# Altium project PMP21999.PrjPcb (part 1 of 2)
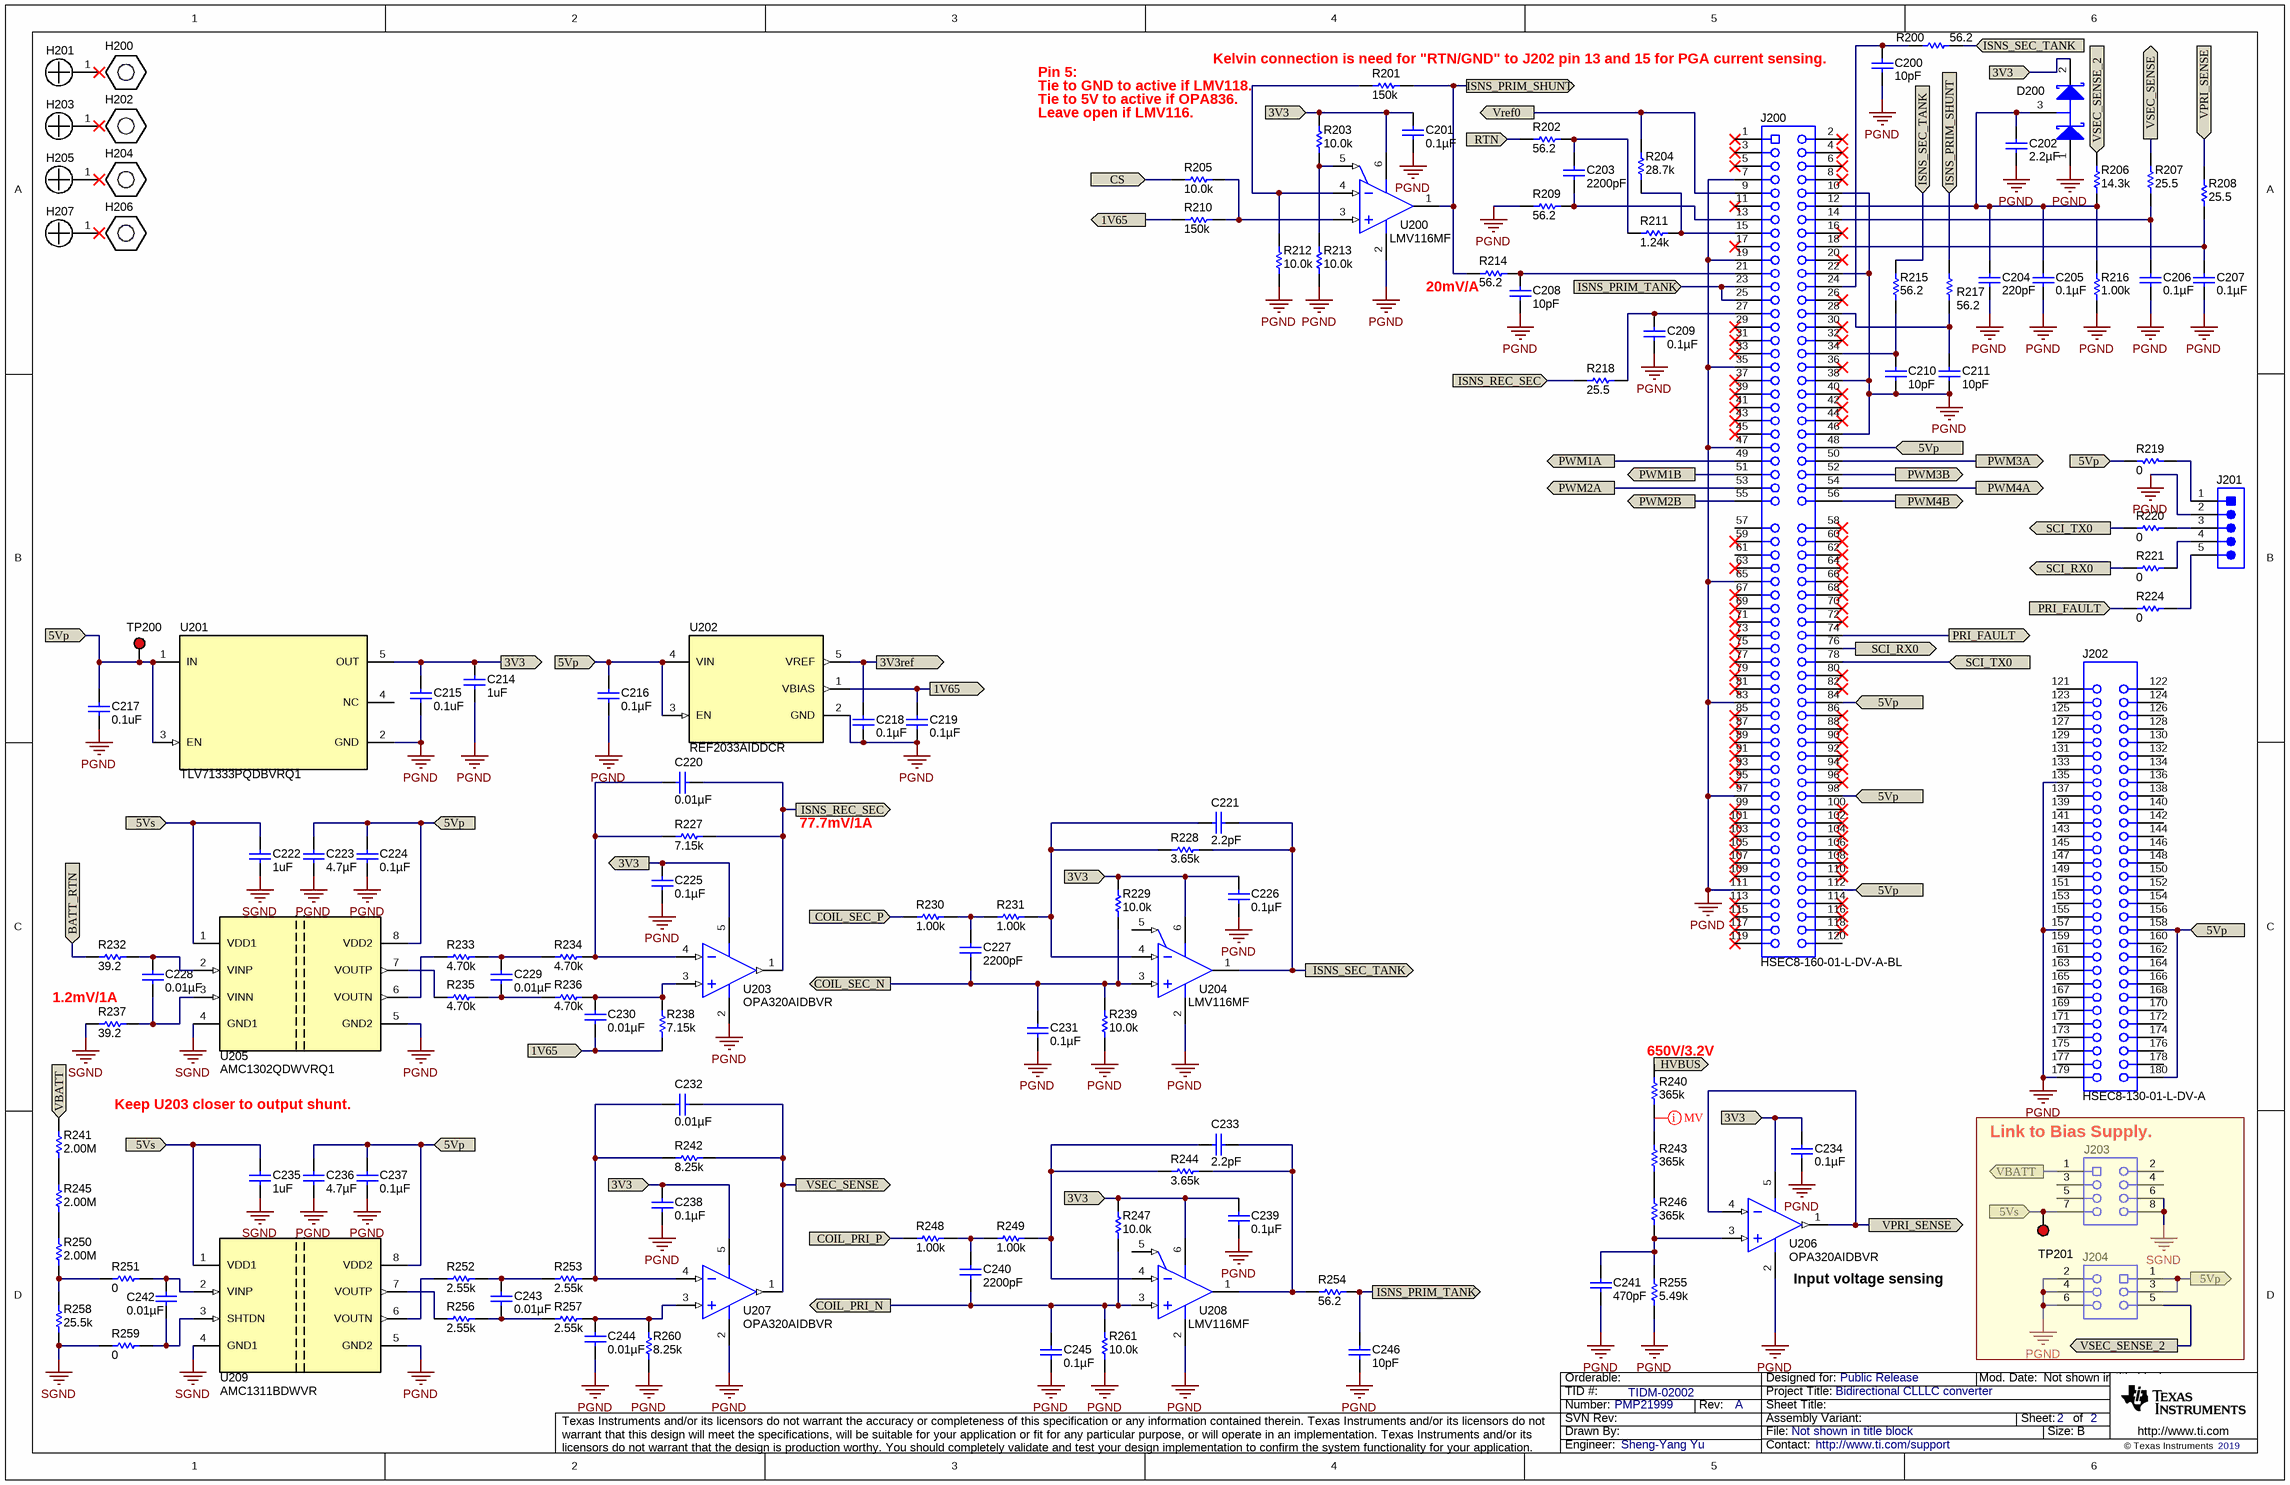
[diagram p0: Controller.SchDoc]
CopyrightYear: 2019; PCB_Layout: Sheng-Yang Yu; PCB_Rev: A; PRJ_Customer: Public Release; PRJ_Engineer: Sheng-Yang Yu; PRJ_Number: PMP21999; PRJ_Title: Bidirectional CLLLC converter; SCH_Rev: A; TechSupport: http://www.ti.com/support; TID: TIDM-02002
2 sheets, 250 parts. Net scope: flat (ports and power ports of the same name join across sheets).
Board file: PMP21999.PcbDoc
Sheets:
  Controller.SchDoc
  PowerStage.SchDoc

## Sheet Controller.SchDoc
size 431 x 279 mm; Date: Not shown in title block; ApprovedBy: Not shown in title block; CheckedBy: Not shown in title block; Author: Not shown in title block; CompanyName: Not shown in title block; Engineer: Not shown in title block; Organization: Not shown in title block; Address1: Not shown in title block; Address2: Not shown in title block; Address3: Not shown in title block; Address4: Not shown in title block; DocumentNumber: 2; Revision: Use project parameter SCH_Rev; SheetNumber: 2; SheetTotal: 2; PageSetup: Record=PageOptions¦CenterHorizontal=True¦CenterVertical=True¦PrintScale=1.00¦XCorrection=1.00¦YCorrection=1.00¦PrintKind=0¦BorderSize=5000000¦LeftOffset=0¦BottomOffset=0¦Orientation=2¦PaperLength=1000¦PaperWidth=1000¦Scale=100¦PaperSource=15¦PrintQuality=600¦MediaType=1¦DitherType=10¦PaperKind=Letter¦PrintScaleMode=1

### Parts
C200  ValueDisplayed: 10pF  [0402]  (hidden comment: C0402C100C8GACTU)
C201  ValueDisplayed: 0.1µF  [0603]  (hidden comment: 06033C104JAT2A)
C202  ValueDisplayed: 2.2µF  [0603]  (hidden comment: GRM188C80J225KE19D)
C203  ValueDisplayed: 2200pF  [0402]  (hidden comment: C0402C222K9RAC7867)
C204  ValueDisplayed: 220pF  [0402]  (hidden comment: AC0402KRX7R9BB221)
C205  ValueDisplayed: 0.1µF  [0603]  (hidden comment: 06033C104JAT2A)
C206  ValueDisplayed: 0.1µF  [0603]  (hidden comment: 06033C104JAT2A)
C207  ValueDisplayed: 0.1µF  [0402]  (hidden comment: C1005X7R1E104M050BB)
C208  ValueDisplayed: 10pF  [0603]  (hidden comment: C0603C100J5GACTU)
C209  ValueDisplayed: 0.1µF  [0603]  (hidden comment: 06033C104JAT2A)
C210  ValueDisplayed: 10pF  [0402]  (hidden comment: C0402C100C8GACTU)
C211  ValueDisplayed: 10pF  [0402]  (hidden comment: C0402C100C8GACTU)
C214  ValueDisplayed: 1uF  [0603]  (hidden comment: C1608X7R1E105K080AB)
C215  ValueDisplayed: 0.1uF  [0402]  (hidden comment: CC0402KRX7R5BB104)
C216  ValueDisplayed: 0.1µF  [0603]  (hidden comment: 06033C104JAT2A)
C217  ValueDisplayed: 0.1uF  [0402]  (hidden comment: CC0402KRX7R5BB104)
C218  ValueDisplayed: 0.1µF  [0603]  (hidden comment: 06033C104JAT2A)
C219  ValueDisplayed: 0.1µF  [0603]  (hidden comment: 06033C104JAT2A)
C220  ValueDisplayed: 0.01µF  [0402]  (hidden comment: GRM155R61A103KA01D)
C221  ValueDisplayed: 2.2pF  [0402]  (hidden comment: GRM1555C1H2R2BA01D)
C222  ValueDisplayed: 1uF  [0603]  (hidden comment: C1608X7R1E105K080AB)
C223  ValueDisplayed: 4.7µF  [0603]  (hidden comment: CGB3B1X5R1A475K055AC)
C224  ValueDisplayed: 0.1µF  [0603]  (hidden comment: 06033C104JAT2A)
C225  ValueDisplayed: 0.1µF  [0402]  (hidden comment: C1005X7R1E104M050BB)
C226  ValueDisplayed: 0.1µF  [0402]  (hidden comment: 0402YC104KAT2A)
C227  ValueDisplayed: 2200pF  [0402]  (hidden comment: CGA2B2X7R1H222K050BA)
C228  ValueDisplayed: 0.01µF  [0603]  (hidden comment: 06031C103KAT2A)
C229  ValueDisplayed: 0.01µF  [0402]  (hidden comment: GRM155R61A103KA01D)
C230  ValueDisplayed: 0.01µF  [0402]  (hidden comment: GRM155R61A103KA01D)
C231  ValueDisplayed: 0.1µF  [0402]  (hidden comment: 0402YC104KAT2A)
C232  ValueDisplayed: 0.01µF  [0402]  (hidden comment: GRM155R61A103KA01D)
C233  ValueDisplayed: 2.2pF  [0402]  (hidden comment: GRM1555C1H2R2BA01D)
C234  ValueDisplayed: 0.1µF  [0805_HV]  (hidden comment: 08053C104JAT2A)
C235  ValueDisplayed: 1uF  [0603]  (hidden comment: C1608X7R1E105K080AB)
C236  ValueDisplayed: 4.7µF  [0603]  (hidden comment: CGB3B1X5R1A475K055AC)
C237  ValueDisplayed: 0.1µF  [0603]  (hidden comment: 06033C104JAT2A)
C238  ValueDisplayed: 0.1µF  [0402]  (hidden comment: C1005X7R1E104M050BB)
C239  ValueDisplayed: 0.1µF  [0402]  (hidden comment: 0402YC104KAT2A)
C240  ValueDisplayed: 2200pF  [0402]  (hidden comment: CGA2B2X7R1H222K050BA)
C241  ValueDisplayed: 470pF  [0402]  (hidden comment: CGA2B2X7R1H471K050BA)
C242  ValueDisplayed: 0.01µF  [0603]  (hidden comment: 06031C103KAT2A)
C243  ValueDisplayed: 0.01µF  [0402]  (hidden comment: GRM155R61A103KA01D)
C244  ValueDisplayed: 0.01µF  [0402]  (hidden comment: GRM155R61A103KA01D)
C245  ValueDisplayed: 0.1µF  [0402]  (hidden comment: 0402YC104KAT2A)
C246  ValueDisplayed: 10pF  [0402]  (hidden comment: C0402C100C8GACTU)
D200  BAT54S-7-F  [SOT-23]  (value not drawn)
H200  1902C  [Keystone_1902C]  (value not drawn)
H201  NY PMS 440 0025 PH  [NY PMS 440 0025 PH]  (value not drawn)
H202  1902C  [Keystone_1902C]  (value not drawn)
H203  NY PMS 440 0025 PH  [NY PMS 440 0025 PH]  (value not drawn)
H204  1902C  [Keystone_1902C]  (value not drawn)
H205  NY PMS 440 0025 PH  [NY PMS 440 0025 PH]  (value not drawn)
H206  1902C  [Keystone_1902C]  (value not drawn)
H207  NY PMS 440 0025 PH  [NY PMS 440 0025 PH]  (value not drawn)
J200  HSEC8-160-01-L-DV-A-BL  [controlCARD-120HSEC]
J201  61300511021  [Wurth_61300511021]  (value not drawn)
J202  HSEC8-130-01-L-DV-A  [controlCARD-180HSEC-60pinAddon]
J203  SSW-104-24-G-D  [Samtec_SSW-104-24-x-D]  (value not drawn)
J204  215307-3  [TE_215307-3]  (value not drawn)
R200  ValueDisplayed: 56.2  [0402]  (hidden comment: RC0402FR-0756R2L)
R201  ValueDisplayed: 150k  [0402]  (hidden comment: CRCW0402150KFKED)
R202  ValueDisplayed: 56.2  [0402]  (hidden comment: RC0402FR-0756R2L)
R203  ValueDisplayed: 10.0k  [0402]  (hidden comment: CRCW040210K0FKED)
R204  ValueDisplayed: 28.7k  [0805_HV]  (hidden comment: CRCW080528K7FKEA)
R205  ValueDisplayed: 10.0k  [0402]  (hidden comment: CRCW040210K0FKED)
R206  ValueDisplayed: 14.3k  [0603]  (hidden comment: CRCW060314K3FKEA)
R207  ValueDisplayed: 25.5  [0603]  (hidden comment: CRCW060325R5FKEA)
R208  ValueDisplayed: 25.5  [0603]  (hidden comment: CRCW060325R5FKEA)
R209  ValueDisplayed: 56.2  [0402]  (hidden comment: RC0402FR-0756R2L)
R210  ValueDisplayed: 150k  [0402]  (hidden comment: CRCW0402150KFKED)
R211  ValueDisplayed: 1.24k  [0402]  (hidden comment: CRCW04021K24FKED)
R212  ValueDisplayed: 10.0k  [0402]  (hidden comment: CRCW040210K0FKED)
R213  ValueDisplayed: 10.0k  [0402]  (hidden comment: CRCW040210K0FKED)
R214  ValueDisplayed: 56.2  [0603]  (hidden comment: CRCW060356R2FKEA)
R215  ValueDisplayed: 56.2  [0402]  (hidden comment: RC0402FR-0756R2L)
R216  ValueDisplayed: 1.00k  [0603]  (hidden comment: CRCW06031K00FKEA)
R217  ValueDisplayed: 56.2  [0402]  (hidden comment: RC0402FR-0756R2L)
R218  ValueDisplayed: 25.5  [0603]  (hidden comment: CRCW060325R5FKEA)
R219  ValueDisplayed: 0  [0603]  (hidden comment: CRCW06030000Z0EA)
R220  ValueDisplayed: 0  [0603]  (hidden comment: CRCW06030000Z0EA)
R221  ValueDisplayed: 0  [0603]  (hidden comment: CRCW06030000Z0EA)
R224  ValueDisplayed: 0  [0603]  (hidden comment: CRCW06030000Z0EA)
R227  ValueDisplayed: 7.15k  [0603]  (hidden comment: CRCW06037K15FKEA)
R228  ValueDisplayed: 3.65k  [0402]  (hidden comment: CRCW04023K65FKED)
R229  ValueDisplayed: 10.0k  [0402]  (hidden comment: CRCW040210K0FKED)
R230  ValueDisplayed: 1.00k  [0402]  (hidden comment: CRCW04021K00FKED)
R231  ValueDisplayed: 1.00k  [0402]  (hidden comment: CRCW04021K00FKED)
R232  ValueDisplayed: 39.2  [0603]  (hidden comment: CRCW060339R2FKEA)
R233  ValueDisplayed: 4.70k  [0402]  (hidden comment: RC0402FR-074K7L)
R234  ValueDisplayed: 4.70k  [0402]  (hidden comment: RC0402FR-074K7L)
R235  ValueDisplayed: 4.70k  [0402]  (hidden comment: RC0402FR-074K7L)
R236  ValueDisplayed: 4.70k  [0402]  (hidden comment: RC0402FR-074K7L)
R237  ValueDisplayed: 39.2  [0603]  (hidden comment: CRCW060339R2FKEA)
R238  ValueDisplayed: 7.15k  [0402]  (hidden comment: CRCW04027K15FKED)
R239  ValueDisplayed: 10.0k  [0402]  (hidden comment: CRCW040210K0FKED)
R240  ValueDisplayed: 365k  [1206]  (hidden comment: CRCW1206365KFKEA)
R241  ValueDisplayed: 2.00M  [1206]  (hidden comment: RC1206FR-072ML)
R242  ValueDisplayed: 8.25k  [0603]  (hidden comment: CRCW06038K25FKEA)
R243  ValueDisplayed: 365k  [1206]  (hidden comment: CRCW1206365KFKEA)
R244  ValueDisplayed: 3.65k  [0402]  (hidden comment: CRCW04023K65FKED)
R245  ValueDisplayed: 2.00M  [1206]  (hidden comment: RC1206FR-072ML)
R246  ValueDisplayed: 365k  [1206]  (hidden comment: CRCW1206365KFKEA)
R247  ValueDisplayed: 10.0k  [0402]  (hidden comment: CRCW040210K0FKED)
R248  ValueDisplayed: 1.00k  [0402]  (hidden comment: CRCW04021K00FKED)
R249  ValueDisplayed: 1.00k  [0402]  (hidden comment: CRCW04021K00FKED)
R250  ValueDisplayed: 2.00M  [1206]  (hidden comment: RC1206FR-072ML)
R251  ValueDisplayed: 0  [0603]  (hidden comment: CRCW06030000Z0EA)
R252  ValueDisplayed: 2.55k  [0603]  (hidden comment: CRCW06032K55FKEA)
R253  ValueDisplayed: 2.55k  [0603]  (hidden comment: CRCW06032K55FKEA)
R254  ValueDisplayed: 56.2  [0402]  (hidden comment: RC0402FR-0756R2L)
R255  ValueDisplayed: 5.49k  [0603]  (hidden comment: CRCW06035K49FKEA)
R256  ValueDisplayed: 2.55k  [0603]  (hidden comment: CRCW06032K55FKEA)
R257  ValueDisplayed: 2.55k  [0603]  (hidden comment: CRCW06032K55FKEA)
R258  ValueDisplayed: 25.5k  [0603]  (hidden comment: CRCW060325K5FKEA)
R259  ValueDisplayed: 0  [0603]  (hidden comment: CRCW06030000Z0EA)
R260  ValueDisplayed: 8.25k  [0603]  (hidden comment: CRCW06038K25FKEA)
R261  ValueDisplayed: 10.0k  [0402]  (hidden comment: CRCW040210K0FKED)
TP200  5000  [Keystone5000]  (value not drawn)
TP201  5000  [Keystone5000]  (value not drawn)
U200  LMV116MF  [DBV0006A_L]
U201  TLV71333PQDBVRQ1  [DBV0005A_N]
U202  REF2033AIDDCR  [DDC0005A_N]
U203  OPA320AIDBVR  [DBV0005A_N]
U204  LMV116MF  [DBV0006A_L]
U205  AMC1302QDWVRQ1  [DWV0008A]
U206  OPA320AIDBVR  [DBV0005A_N]
U207  OPA320AIDBVR  [DBV0005A_N]
U208  LMV116MF  [DBV0006A_L]
U209  AMC1311BDWVR  [DWV0008A]

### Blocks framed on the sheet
Link to Bias Supply.: J203 J204 TP201

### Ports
1V65, 1V65 (in), 1V65 (out), 3V3, 3V3 (in), 3V3 (out), 3V3ref (out), 5Vp, 5Vp (in), 5Vs, BATT_RTN, COIL_PRI_N (out), COIL_PRI_P (in), COIL_SEC_N (out), COIL_SEC_P (in), CS (in), HVBUS (in), ISNS_PRIM_SHUNT (in), ISNS_PRIM_SHUNT (out), ISNS_PRIM_TANK (in), ISNS_PRIM_TANK (out), ISNS_REC_SEC (in), ISNS_REC_SEC (out), ISNS_SEC_TANK (in), ISNS_SEC_TANK (out), PRI_FAULT (in), PRI_FAULT (out), PWM1A, PWM1B, PWM2A (out), PWM2B (out), PWM3A (out), PWM3B (out), PWM4A (out), PWM4B (out), RTN (in), SCI_RX0 (out), SCI_TX0, VBATT, VBATT (in), VPRI_SENSE (in), VPRI_SENSE (out), Vref0 (out), VSEC_SENSE, VSEC_SENSE_2, VSEC_SENSE_2 (out)

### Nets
PGND: C200.2 C201.1 C202.2 C204.2 C205.2 C206.1 C207.2 C208.2 C209.2 C210.2 C211.2 C214.1 C215.2 C216.1 C217.2 C218.1 C219.1 C223.2 C224.1 C225.2 C226.2 C231.2 C234.2 C236.2 C237.1 C238.2 C239.2 C241.2 C244.2 C245.2 C246.2 D200.1(A) J200.7 J200.10 J200.19 J200.22 J200.35 J200.38 J200.46 J200.47 J200.65 J200.83 J200.97 J200.111 J201.2 J202.135 J202.157 J202.179 J204.2 J204.4 J204.6 R209.1 R212.1 R213.1 R216.1 R239.1 R255.1 R260.1 R261.1 U200.2(VS-) U201.2(GND) U202.2(GND) U203.2(V-) U204.2(VS-) U205.5(GND2) U206.2(V-) U207.2(V-) U208.2(VS-) U209.5(GND2)
SGND: C222.1 C235.1 J203.6 J203.8 R237.1 R258.1 R259.1 U205.4(GND1) U209.4(GND1)
1V65: C219.2 C230.2 R210.1 R238.1 U202.1(VBIAS) ; port 1V65
3V3: C201.2 C214.2 C215.1 C225.1 C226.1 C234.1 C238.1 C239.1 D200.2(K) R203.2 R229.2 R247.2 U200.6(VS+) U201.5(OUT) U203.5(V+) U204.6(VS+) U206.5(V+) U207.5(V+) U208.6(VS+) ; port 3V3
3V3ref: C218.2 U202.5(VREF) ; port 3V3ref
5Vp: C216.2 C217.1 C223.1 C224.2 C236.1 C237.2 J200.48 J200.84 J200.98 J200.112 J202.158 J202.180 J204.1 J204.3 R219.2 TP200.1 U201.1(IN) U201.3(EN) U202.3(EN) U202.4(VIN) U205.8(VDD2) U209.8(VDD2) ; port 5Vp
5Vs: C222.2 C235.2 J203.7 TP201.1 U205.1(VDD1) U209.1(VDD1) ; port 5Vs
BATT_RTN: R232.1 ; port BATT_RTN
COIL_PRI_N: C240.2 C245.1 R247.1 R261.2 U208.3(VIN+) ; port COIL_PRI_N
COIL_PRI_P: R248.1 ; port COIL_PRI_P
COIL_SEC_N: C227.2 C231.1 R229.1 R239.2 U204.3(VIN+) ; port COIL_SEC_N
COIL_SEC_P: R230.1 ; port COIL_SEC_P
CS: R205.2 ; port CS
HVBUS: R240.2 ; port HVBUS
ISNS_PRIM_SHUNT: R201.2 R214.1 R217.2 U200.1(VOUT) ; port ISNS_PRIM_SHUNT
ISNS_PRIM_TANK: C246.1 J200.23 J200.25 R254.1 ; port ISNS_PRIM_TANK
ISNS_REC_SEC: C220.1 R218.2 R227.2 U203.1(OUT) ; port ISNS_REC_SEC
ISNS_SEC_TANK: C221.1 R200.2 R215.2 R228.2 U204.1(VOUT) ; port ISNS_SEC_TANK
PRI_FAULT: J200.74 R224.1 ; port PRI_FAULT
PWM1A: J200.49 ; port PWM1A
PWM1B: J200.51 ; port PWM1B
PWM2A: J200.53 ; port PWM2A
PWM2B: J200.55 ; port PWM2B
PWM3A: J200.50 ; port PWM3A
PWM3B: J200.52 ; port PWM3B
PWM4A: J200.54 ; port PWM4A
PWM4B: J200.56 ; port PWM4B
RTN: R202.1 ; port RTN
SCI_RX0: J200.76 R221.1 ; port SCI_RX0
SCI_TX0: J200.78 R220.1 ; port SCI_TX0
VBATT: J203.1 R241.2 ; port VBATT
VPRI_SENSE: R208.2 U206.1(OUT) U206.4(IN-) ; port VPRI_SENSE
Vref0: J200.9 R204.2 ; port Vref0
VSEC_SENSE: C232.1 R207.2 R242.2 U207.1(OUT) ; port VSEC_SENSE
VSEC_SENSE_2: J204.5 R206.2 ; port VSEC_SENSE_2
NetC200_1: C200.1 J200.24 R200.1
NetC202_1: C202.1 C204.1 C205.1 D200.3(C) J200.12 R206.1 R216.2
NetC203_1: C203.1 R202.2 R211.1
NetC203_2: C203.2 J200.13 R209.2
NetC206_2: C206.2 J200.14 R207.1
NetC207_1: C207.1 J200.18 R208.1
NetC208_1: C208.1 J200.21 R214.2
NetC209_1: C209.1 J200.27 R218.1
NetC210_1: C210.1 J200.34 R215.1
NetC211_1: C211.1 J200.28 R217.1
NetC220_2: C220.2 R227.1 R234.2 U203.4(IN-)
NetC221_2: C221.2 R228.1 R231.2 U204.4(VIN-)
NetC227_1: C227.1 R230.2 R231.1
NetC228_1: C228.1 R232.2 U205.2(VINP)
NetC228_2: C228.2 R237.2 U205.3(VINN)
NetC229_1: C229.1 R233.2 R234.1
NetC229_2: C229.2 R235.2 R236.1
NetC230_1: C230.1 R236.2 R238.2 U203.3(IN+)
NetC232_2: C232.2 R242.1 R253.2 U207.4(IN-)
NetC233_1: C233.1 R244.2 R254.2 U208.1(VOUT)
NetC233_2: C233.2 R244.1 R249.2 U208.4(VIN-)
NetC240_1: C240.1 R248.2 R249.1
NetC241_1: C241.1 R246.1 R255.2 U206.3(IN+)
NetC242_1: C242.1 R251.2 U209.2(VINP)
NetC242_2: C242.2 R259.2 U209.3(SHTDN)
NetC243_1: C243.1 R252.2 R253.1
NetC243_2: C243.2 R256.2 R257.1
NetC244_1: C244.1 R257.2 R260.2 U207.3(IN+)
NetJ200_15: J200.15 R204.1 R211.2
NetJ201_1: J201.1 R219.1
NetJ201_3: J201.3 R220.2
NetJ201_4: J201.4 R221.2
NetJ201_5: J201.5 R224.2
NetR201_1: R201.1 R212.2 U200.4(VIN-)
NetR203_1: R203.1 R213.2 U200.5(~{PD})
NetR205_1: R205.1 R210.2 U200.3(VIN+)
NetR233_1: R233.1 U205.6(VOUTN)
NetR235_1: R235.1 U205.7(VOUTP)
NetR240_1: R240.1 R243.2
NetR241_1: R241.1 R245.2
NetR243_1: R243.1 R246.2
NetR245_1: R245.1 R250.2
NetR250_1: R250.1 R251.1 R258.2
NetR252_1: R252.1 U209.6(VOUTN)
NetR256_1: R256.1 U209.7(VOUTP)

Not connected (* = marked no-connect by the designer): H201 1*; H203 1*; H205 1*; H207 1*; J200 1* 2* 3* 4* 5* 6* 8* 11* 16* 17* 20* 26* 29* 30* 31* 32* 33* 36* 37* 39* 40* 41* 42* 43* 44* 45* 57 58* 59* 60* 61 62* 63* 64* 66* 67* 68* 69* 70* 71* 72* 73* 75* 77* 79* 80* 81* 82* 85* 86* 87* 88* 89* 90* 91* 92* 93* 94* 95* 96* 99* 100* 101* 102* 103* 104* 105* 106* 107* 108* 109* 110* 113* 114* 115* 116* 117* 118* 119* 120; J202 121 122 123 124 125 126 127 128 129 130 131 132 133 134 136 137 138 139 140 141 142 143 144 145 146 147 148 149 150 151 152 153 154 155 156 159 160 161 162 163 164 165 166 167 168 169 170 171 172 173 174 175 176 177 178; J203 2 3 4 5; U201 4(NC); U204 5(~{PD}); U208 5(~{PD})

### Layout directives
net class MV: NetR240_1

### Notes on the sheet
- Pin 5:
- Tie to GND to active if LMV118.
- Tie to 5V to active if OPA836.
- (near R201) Kelvin connection is need for "RTN/GND" to J202 pin 13 and 15 for PGA current sensing.
- Leave open if LMV116.
- (near R214) 20mV/A
- 77.7mV/1A
- 1.2mV/1A
- Keep U203 closer to output shunt.
- (near R240) 650V/3.2V
- (near U206) Input voltage sensing

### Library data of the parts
C200 C210 C211 C246 = C0402C100C8GACTU: CAP, CERM, 10 pF, 10 V,+/- 2.5%, C0G/NP0, 0402; Manufacturer: Kemet; Polarized: N; CompType: Capacitor; Value: 10pF; U/M: EA; Cap_F: 0.00000000001; Tolerance_%: 2.5; VDC_V: 10; Value2: 10V; TaMin_C: -55; TaMax_C: 125; SizeArea_mm2: 0.5; SizeAreaWB_mm2: 3; SizeX_mm: 1; SizeZ_mm: 0.6; AEC Category: Q200
C201 C205 C206 C209 C216 C218 C219 C224 C237 = 06033C104JAT2A: CAP, CERM, 0.1uF, 25V, +/-5%, X7R, 0603; Manufacturer: AVX; Polarized: N; CompType: Capacitor; U/M: EA; Cap_F: 0.0000001; Tolerance_%: 5; ESR_Ohm: 0.05; Value1: 0.05 ohm; VDC_V: 25; TaMin_C: -55; TaMax_C: 125
C202 = GRM188C80J225KE19D: CAP, CERM, 2.2 µF, 6.3 V,+/- 10%, X6S, 0603; Manufacturer: MuRata; Polarized: N; CompType: Capacitor; Value: 2.2uF; U/M: EA; Cap_F: 0.0000022; Tolerance_%: 10; VDC_V: 6.3; Value2: 6.3V; TaMin_C: -55; TaMax_C: 105; SizeArea_mm2: 1.28; SizeAreaWB_mm2: 4.68; SizeX_mm: 1.6; SizeY_mm: 0.8; SizeZ_mm: 1; AEC Category: Q200
C203 = GRM155R60J222KA01D: CAP CER 2200PF 6.3V X7R 0402; Manufacturer: KEMET; Polarized: N; CompType: Capacitor; U/M: EA; Cap_F: 0.0000000022; Tolerance_%: 10; VDC_V: 6.3; TaMin_C: -55; TaMax_C: 85; SizeArea_mm2: 0.5; SizeAreaWB_mm2: 3; SizeX_mm: 1; SizeZ_mm: 0.6; AEC Category: Q200
C204 = GRM1555C1H221JA01D: CAP, CERM, 220 pF, 50 V,+/- 5%, C0G/NP0, 0402; Manufacturer: Yageo; Polarized: N; CompType: Capacitor; Value: 220pF; U/M: EA; Cap_F: 0.00000000022; Tolerance_%: 5; VDC_V: 50; Value2: 50V; TaMin_C: -55; TaMax_C: 125; SizeArea_mm2: 0.5; SizeAreaWB_mm2: 3; SizeX_mm: 1; SizeZ_mm: 0.6; AEC Category: Q200; Green_Lifecycle: Active; Green_REACh: Passed
C207 C225 C238 = C1005X7R1E104M050BB: CAP, CERM, 0.1 µF, 25 V,+/- 20%, X7R, 0402; Manufacturer: TDK; Polarized: N; CompType: Capacitor; Value: 0.1uF; U/M: EA; Cap_F: 0.0000001; Tolerance_%: 20; VDC_V: 25; Value2: 25V; TaMin_C: -55; TaMax_C: 125; SizeArea_mm2: 0.5; SizeAreaWB_mm2: 3; SizeX_mm: 1; SizeZ_mm: 0.6; AEC Category: Q200; Green_Lifecycle: NRND; Green_REACh: Passed
C208 = C0603C100J5GACTU: CAP, CERM, 10 pF, 50 V,+/- 5%, C0G/NP0, 0603; Manufacturer: Kemet; Polarized: N; CompType: Capacitor; Value: 10pF; U/M: EA; Cap_F: 0.00000000001; Tolerance_%: 5; VDC_V: 50; Value2: 50V; TaMin_C: -55; TaMax_C: 125; SizeArea_mm2: 1.28; SizeAreaWB_mm2: 4.68; SizeX_mm: 1.6; SizeY_mm: 0.8; SizeZ_mm: 1; AEC Category: Q200; Green_Lifecycle: Active; Green_REACh: Passed
C214 C222 C235 = C1608X7R1E105K080AB: CAP, CERM, 1uF, 25V, +/-10%, X7R, 0603; Manufacturer: TDK; Polarized: N; CompType: Capacitor; U/M: EA; Cap_F: 0.000001; Tolerance_%: 10; Value1: Unknown; VDC_V: 25; TaMin_C: -55; TaMax_C: 125
C215 C217 = GRM155R70J104KA01D: CAP, CERM, 0.1uF, 6.3V, +/-10%, X7R, 0402; Manufacturer: Yageo; Polarized: N; CompType: Capacitor; U/M: EA; Cap_F: 0.0000001; Tolerance_%: 10; Value1: Unknown; VDC_V: 6.3; TaMin_C: -55; TaMax_C: 125
C220 C229 C230 C232 C243 C244 = GRM155R61A103KA01D: CAP, CERM, 0.01 µF, 10 V,+/- 10%, X5R, 0402; Manufacturer: MuRata; Polarized: N; CompType: Capacitor; Value: 0.01uF; U/M: EA; Cap_F: 0.00000001; Tolerance_%: 10; Value2: 10V; TaMin_C: -55; TaMax_C: 85; SizeArea_mm2: 0.5; SizeAreaWB_mm2: 3; SizeX_mm: 1; SizeZ_mm: 0.6; AEC Category: Q200; Green_Lifecycle: Active; Green_REACh: Passed
C221 C233 = GRM1555C1H2R2BA01D: CAP, CERM, 2.2 pF, 50 V,+/- 5%, C0G/NP0, 0402; Manufacturer: MuRata; Polarized: N; CompType: Capacitor; Value: 2.2pF; U/M: EA; Cap_F: 0.0000000000022; Tolerance_%: 5; VDC_V: 50; Value2: 50V; TaMin_C: -55; TaMax_C: 125; SizeArea_mm2: 0.5; SizeAreaWB_mm2: 3; SizeX_mm: 1; SizeZ_mm: 0.6; AEC Category: Q200
C223 C236 = CGB3B1X5R1A475K055AC: CAP, CERM, 4.7 µF, 10 V,+/- 10%, X5R, 0603; Manufacturer: TDK; Polarized: N; CompType: Capacitor; Value: 4.7uF; U/M: EA; Cap_F: 0.0000047; Tolerance_%: 10; Value2: 10V; TaMin_C: -55; TaMax_C: 85; SizeArea_mm2: 1.28; SizeAreaWB_mm2: 4.68; SizeX_mm: 1.6; SizeY_mm: 0.8; SizeZ_mm: 1; AEC Category: Q200; Green_Lifecycle: Active; Green_REACh: Passed
C226 C231 C239 C245 = 0402YC104KAT2A: CAP, CERM, 0.1 µF, 16 V,+/- 10%, X7R, 0402; Manufacturer: AVX; Polarized: N; CompType: Capacitor; Value: 0.1uF; U/M: EA; Cap_F: 0.0000001; Tolerance_%: 10; VDC_V: 16; Value2: 16V; TaMin_C: -55; TaMax_C: 125; SizeArea_mm2: 0.5; SizeAreaWB_mm2: 3; SizeX_mm: 1; SizeZ_mm: 0.6; AEC Category: Q200; Green_Lifecycle: Active; Green_REACh: Passed
C227 C240 = CGA2B2X7R1H222K050BA: CAP, CERM, 2200 pF, 50 V,+/- 10%, X7R, AEC-Q200 Grade 1, 0402; Manufacturer: TDK; Polarized: N; CompType: Capacitor; Value: 2200pF; U/M: EA; Cap_F: 0.0000000022; Tolerance_%: 10; ESR_ohm: 1.07794; Value1: 1.07794 ohm; VDC_V: 50; Value2: 50V; IRMS_A: 0.264071; TaMin_C: -55; TaMax_C: 125; SizeArea_mm2: 0.5; SizeAreaWB_mm2: 3; SizeX_mm: 1; SizeZ_mm: 0.6; AEC Category: Q200; AEC Qualified: Y
C228 C242 = 06031C103KAT2A: CAP, CERM, 0.01 µF, 100 V,+/- 10%, X7R, 0603; Manufacturer: AVX; Polarized: N; CompType: Capacitor; Value: 0.01uF; U/M: EA; Cap_F: 0.00000001; Tolerance_%: 10; ESR_ohm: 0.098; Value1: 0.098 ohm; VDC_V: 100; Value2: 100V; TaMin_C: -55; TaMax_C: 125; SizeArea_mm2: 1.28; SizeAreaWB_mm2: 4.68; SizeX_mm: 1.6; SizeY_mm: 0.8; SizeZ_mm: 1; AEC Category: Q200; Green_Lifecycle: Active; Green_REACh: Passed
C234 = 08053C104JAT2A: CAP, CERM, 0.1 µF, 25 V,+/- 5%, X7R, 0805; Manufacturer: AVX; Polarized: N; CompType: Capacitor; Value: 0.1uF; U/M: EA; Cap_F: 0.0000001; Tolerance_%: 5; VDC_V: 25; Value2: 25V; TaMin_C: -55; TaMax_C: 125; Cap_Case: 0805; SizeArea_mm2: 2.5; SizeAreaWB_mm2: 6.75; SizeX_mm: 2; SizeY_mm: 1.25; SizeZ_mm: 1.45; AEC Category: Q200
C241 = CGA2B2X7R1H471K050BA: CAP, CERM, 470 pF, 50 V,+/- 10%, X7R, AEC-Q200 Grade 1, 0402; Manufacturer: TDK; Polarized: N; CompType: Capacitor; Value: 470pF; U/M: EA; Cap_F: 0.00000000047; Tolerance_%: 10; ESR_ohm: 4.96489; Value1: 4.96489 ohm; VDC_V: 50; Value2: 50V; IRMS_A: 0.228414; TaMin_C: -55; TaMax_C: 125; SizeArea_mm2: 0.5; SizeAreaWB_mm2: 3; SizeX_mm: 1; SizeZ_mm: 0.6; AEC Category: Q200; AEC Qualified: Y
D200 = CMP-0028456-1: Diode, Schottky, 30 V, 0.2 A, SOT-23; Manufacturer: Diodes Inc.; Io_A: 2dA; Green_Lifecycle: Active; SizeAreaWB_mm2: 14; Vr_V: 30V; Green_REACh: Passed; Value1: 0.2A; TJmax_C: 125°C; U/M: EA; Value: 30V; SizeZ_mm: 1.1; SizeX_mm: 2.5; SizeY_mm: 3; Vf_V: 6.5dV; Value2: 0.65V; SizeArea_mm2: 7.5; AEC Category: Q101
H200 H202 H204 H206 = CMP-0003610-1: Standoff, Hex, 0.5"L #4-40 Nylon; Manufacturer: Keystone; CompType: Hardware
H201 H203 H205 H207 = CMP-0003617-1: Machine Screw, Round, #4-40 x 1/4, Nylon, Philips panhead; Manufacturer: B&F Fastener Supply; CompType: Hardware
J200 = controlCARD-120HSEC: C2000 controlCARD-120HSEC connector, SMT; Manufacturer: Samtec; SymbolCreator: a0412235; Note: The pin numbering does not match Samtec datasheet
J201 = CMP-0054800-1: Header, 2.54 mm, 5x1, Gold, R/A, TH; Manufacturer: Wurth Elektronik; CNHeader: TRUE; Shrouded: N; Gender: Male; Row_Count: 1; Pitch_mm: 2.54; CT: FALSE
J202 = CMP-0003859-2: C2000 controlCARD-180HSEC (60-pin addon) connector, SMT; Manufacturer: Samtec; Note: The pin numbering does not match Samtec datasheet
J203 = CMP-0055706-1: Receptacle, 2.54mm, 4x2, Gold, TH; Manufacturer: Samtec; CNHeader: FALSE; Current_A: 4.7A; Gender: Female; Cert_CSA: Y; Voltage_V: 465V; CompType: Socket Strip; Row_Count: 2; RowSpacing_mm: 2.54; CT: TRUE
J204 = CMP-0082603-1: Receptacle, 2.54mm, 3x2, Tin, TH; Manufacturer: TE Connectivity; Pitch_mm: 2.54; Gender: Female; Cert_UL: Y; Row_Count: 2; CompType: Socket Strip
R200 R202 R209 R215 R217 R254 = CRCW040256R2FKED: RES SMD 56.2 OHM 1% 1/16W 0402; Manufacturer: Yageo; CompType: Resistor; Value: 56.2; Value_Code: 56R2; Tolerance_%: 1; Power_W: 0.063; Value2: 0.063W; VDC_V: 50; TempCo: 100 ppm/C; SizeArea_mm2: 0.5; SizeZ_mm: 0.6; EIA_Code: E96; U/M: EA; AEC Category: Q200
R201 R210 = CRCW0402150KFKED: RES, 150 k, 1%, 0.063 W, 0402; Manufacturer: Vishay-Dale; CompType: Resistor; Value: 150k; Res_ohm: 150000; Tolerance_%: 1; Power_W: 0.063; Value2: 0.063W; VDC_V: 50; TempCo: 100 ppm/C; SizeArea_mm2: 0.5; SizeZ_mm: 0.6; EIA_Code: E96; U/M: EA; AEC Category: Q200; Green_Lifecycle: Active; Green_REACh: Passed
R203 R205 R212 R213 R229 R239 R247 R261 = CRCW040210K0FKED: RES, 10.0 k, 1%, 0.063 W, 0402; Manufacturer: Vishay-Dale; CompType: Resistor; Value: 10.0k; Res_ohm: 10000; Value_Code: 10k0; Tolerance_%: 1; Power_W: 0.063; Value2: 0.063W; VDC_V: 50; TempCo: 100 ppm/C; SizeArea_mm2: 0.5; SizeZ_mm: 0.6; EIA_Code: E96; U/M: EA; AEC Category: Q200; Green_Lifecycle: Active; Green_REACh: Passed
R204 = CRCW080528K7FKEA: RES, 28.7 k, 1%, 0.125 W, 0805; Manufacturer: Vishay-Dale; CompType: Resistor; Value: 28.7k; Res_ohm: 28700; Value_Code: 28k7; Tolerance_%: 1; Power_W: 0.125; Value2: 0.125W; VDC_V: 150; TempCo: 100 ppm/C; SizeArea_mm2: 2.5; SizeX_mm: 2; SizeY_mm: 1.25; SizeZ_mm: 1.45; EIA_Code: E96; U/M: EA; AEC Category: Q200
R206 = CRCW060314K3FKEA: RES, 14.3 k, 1%, 0.1 W, 0603; Manufacturer: Vishay-Dale; CompType: Resistor; Value: 14.3k; Res_ohm: 14300; Value_Code: 14k3; Tolerance_%: 1; Power_W: 0.1; Value2: 0.1W; VDC_V: 75; TempCo: 100 ppm/C; SizeArea_mm2: 1.28; SizeX_mm: 1.6; SizeY_mm: 0.8; EIA_Code: E96; U/M: EA; AEC Category: Q200; Green_Lifecycle: Active; Green_REACh: Passed
R207 R218 = CMP-0022243-4: RES, 25.5, 1%, 0.1 W, AEC-Q200 Grade 0, 0603; Manufacturer: Vishay-Dale; Power_W: 100mW; TempCo: 100 ppm/C; Value_Code: 25R5; Value: 25.5; EIA_Code: E96; SizeX_mm: 1.6; SizeY_mm: 0.8; SizeZ_mm: 1; Value2: 0.1W; SizeArea_mm2: 1.28; CompType: Resistor; AEC Qualified: Y; VDC_V: 75V; AEC Category: Q200; AEC Grade: 0
R208 = CRCW060325R5FKEA: RES, 25.5, 1%, 0.1 W, 0603; Manufacturer: Vishay-Dale; CompType: Resistor; Value: 25.5; Value_Code: 25R5; Tolerance_%: 1; Power_W: 0.1; Value2: 0.1W; VDC_V: 75; TempCo: 100 ppm/C; SizeArea_mm2: 1.28; SizeX_mm: 1.6; SizeY_mm: 0.8; EIA_Code: E96; U/M: EA; AEC Category: Q200
R211 = CRCW04021K24FKED: RES, 1.24 k, 1%, 0.063 W, 0402; Manufacturer: Vishay-Dale; CompType: Resistor; Value: 1.24k; Res_ohm: 1240; Value_Code: 1k24; Tolerance_%: 1; Power_W: 0.063; Value2: 0.063W; VDC_V: 50; TempCo: 100 ppm/C; SizeArea_mm2: 0.5; SizeZ_mm: 0.6; EIA_Code: E96; U/M: EA; AEC Category: Q200
R214 = CRCW060356R2FKEA: RES, 56.2, 1%, 0.1 W, 0603; Manufacturer: Vishay-Dale; CompType: Resistor; Value: 56.2; Value_Code: 56R2; Tolerance_%: 1; Power_W: 0.1; Value2: 0.1W; VDC_V: 75; TempCo: 100 ppm/C; SizeArea_mm2: 1.28; SizeX_mm: 1.6; SizeY_mm: 0.8; EIA_Code: E96; U/M: EA; AEC Category: Q200; Green_Lifecycle: Active; Green_REACh: Passed
R216 = CRCW06031K00FKEA: RES, 1.00 k, 1%, 0.1 W, 0603; Manufacturer: Vishay-Dale; CompType: Resistor; Value: 1.00k; Res_ohm: 1000; Value_Code: 1k00; Tolerance_%: 1; Power_W: 0.1; Value2: 0.1W; VDC_V: 75; TempCo: 100 ppm/C; SizeArea_mm2: 1.28; SizeX_mm: 1.6; SizeY_mm: 0.8; EIA_Code: E96; U/M: EA; AEC Category: Q200; Green_Lifecycle: Active; Green_REACh: Passed
R219-R221 R224 R251 R259 = CRCW06030000Z0EA: RES, 0, 5%, 0.1 W, 0603; Manufacturer: Vishay-Dale; CompType: Resistor; Value: 0; Value_Code: 0000; Tolerance_%: 5; Power_W: 0.1; Value2: 0.1W; VDC_V: 75; TempCo: 200 ppm/C; SizeArea_mm2: 1.28; SizeX_mm: 1.6; SizeY_mm: 0.8; SizeZ_mm: 1; EIA_Code: E24; U/M: EA; AEC Category: Q200; Green_Lifecycle: Active; Green_REACh: Passed
R227 = CMP-0022599-4: RES, 7.15 k, 1%, 0.1 W, AEC-Q200 Grade 0, 0603; Manufacturer: Vishay-Dale; Power_W: 100mW; TempCo: 100 ppm/C; Value_Code: 7k15; Value: 7.15k; EIA_Code: E96; SizeX_mm: 1.6; SizeY_mm: 0.8; SizeZ_mm: 1; Value2: 0.1W; SizeArea_mm2: 1.28; CompType: Resistor; AEC Qualified: Y; VDC_V: 75V; AEC Category: Q200; AEC Grade: 0
R228 R244 = CRCW04023K65FKED: RES, 3.65 k, 1%, 0.063 W, 0402; Manufacturer: Vishay-Dale; CompType: Resistor; Value: 3.65k; Res_ohm: 3650; Value_Code: 3k65; Tolerance_%: 1; Power_W: 0.063; Value2: 0.063W; VDC_V: 50; TempCo: 100 ppm/C; SizeArea_mm2: 0.5; SizeZ_mm: 0.6; EIA_Code: E96; U/M: EA; AEC Category: Q200
R230 R231 R248 R249 = CRCW04021K00FKED: RES, 1.00 k, 1%, 0.063 W, 0402; Manufacturer: Vishay-Dale; CompType: Resistor; Value: 1.00k; Res_ohm: 1000; Value_Code: 1k00; Tolerance_%: 1; Power_W: 0.063; Value2: 0.063W; VDC_V: 50; TempCo: 100 ppm/C; SizeArea_mm2: 0.5; SizeZ_mm: 0.6; EIA_Code: E96; U/M: EA; AEC Category: Q200; Green_Lifecycle: Active; Green_REACh: Passed
R232 R237 = CRCW060339R2FKEA: RES, 39.2, 1%, 0.1 W, 0603; Manufacturer: Vishay-Dale; CompType: Resistor; Value: 39.2; Value_Code: 39R2; Tolerance_%: 1; Power_W: 0.1; Value2: 0.1W; VDC_V: 75; TempCo: 100 ppm/C; SizeArea_mm2: 1.28; SizeX_mm: 1.6; SizeY_mm: 0.8; EIA_Code: E96; U/M: EA; AEC Category: Q200
R233-R236 = CMP-0026739-1: RES, 4.70 k, 1%, 0.0625 W, 0402; Manufacturer: Yageo America; Power_W: 62.5mW; TempCo: 100 ppm/C; Value_Code: 4k70; U/M: EA; Value: 4.70k; Res_ohm: 4.7k; SizeX_mm: 1; SizeY_mm: 0.5; SizeZ_mm: 0.6; CompType: Resistor; AEC Qualified: N; VDC_V: 50V; AEC Category: Q200
R238 = CRCW04027K15FKED: RES, 7.15 k, 1%, 0.063 W, 0402; Manufacturer: Vishay-Dale; CompType: Resistor; Value: 7.15k; Res_ohm: 7150; Value_Code: 7k15; Tolerance_%: 1; Power_W: 0.063; Value2: 0.063W; VDC_V: 50; TempCo: 100 ppm/C; SizeArea_mm2: 0.5; SizeZ_mm: 0.6; EIA_Code: E96; U/M: EA; AEC Category: Q200; Green_Lifecycle: Active; Green_REACh: Passed
R240 R243 R246 = CMP-0016927-3: RES, 365 k, 1%, 0.25 W, AEC-Q200 Grade 0, 1206; Manufacturer: Vishay-Dale; Power_W: 250mW; TempCo: 100 ppm/C; Value: 365k; EIA_Code: E96; SizeX_mm: 3.2; SizeY_mm: 1.6; SizeZ_mm: 1.35; Value2: 0.25W; SizeArea_mm2: 5.12; CompType: Resistor; AEC Qualified: Y; VDC_V: 200V; AEC Category: Q200; AEC Grade: 0
R241 R245 R250 = RC1206FR-072ML: RES, 2.00 M, 1%, 0.25 W, 1206; Manufacturer: Yageo America; CompType: Resistor; Value: 2.00Meg; Res_ohm: 2000000; Value_Code: 2M00; Tolerance_%: 1; Power_W: 0.25; Value2: 0.25W; VDC_V: 200; TempCo: 100 ppm/C; SizeArea_mm2: 5.12; SizeX_mm: 3.2; SizeY_mm: 1.6; SizeZ_mm: 1.35; EIA_Code: E96; U/M: EA; AEC Category: Q200; Green_Lifecycle: Active; Green_REACh: Passed
R242 R260 = CMP-0022635-4: RES, 8.25 k, 1%, 0.1 W, AEC-Q200 Grade 0, 0603; Manufacturer: Vishay-Dale; Power_W: 100mW; TempCo: 100 ppm/C; Value_Code: 8k25; Value: 8.25k; EIA_Code: E96; SizeX_mm: 1.6; SizeY_mm: 0.8; SizeZ_mm: 1; Value2: 0.1W; SizeArea_mm2: 1.28; CompType: Resistor; AEC Qualified: Y; VDC_V: 75V; AEC Category: Q200; AEC Grade: 0
R252 R253 R256 R257 = CMP-0022278-4: RES, 2.55 k, 1%, 0.1 W, AEC-Q200 Grade 0, 0603; Manufacturer: Vishay-Dale; Power_W: 100mW; TempCo: 100 ppm/C; Value_Code: 2k55; Value: 2.55k; EIA_Code: E96; SizeX_mm: 1.6; SizeY_mm: 0.8; SizeZ_mm: 1; Value2: 0.1W; SizeArea_mm2: 1.28; CompType: Resistor; AEC Qualified: Y; VDC_V: 75V; AEC Category: Q200; AEC Grade: 0
R255 = CMP-0022512-4: RES, 5.49 k, 1%, 0.1 W, AEC-Q200 Grade 0, 0603; Manufacturer: Vishay-Dale; Power_W: 100mW; TempCo: 100 ppm/C; Value_Code: 5k49; Value: 5.49k; EIA_Code: E96; SizeX_mm: 1.6; SizeY_mm: 0.8; SizeZ_mm: 1; Value2: 0.1W; SizeArea_mm2: 1.28; CompType: Resistor; AEC Qualified: Y; VDC_V: 75V; AEC Category: Q200; AEC Grade: 0
R258 = CMP-0022242-4: RES, 25.5 k, 1%, 0.1 W, AEC-Q200 Grade 0, 0603; Manufacturer: Vishay-Dale; Power_W: 100mW; TempCo: 100 ppm/C; Value_Code: 25k5; Value: 25.5k; EIA_Code: E96; SizeX_mm: 1.6; SizeY_mm: 0.8; SizeZ_mm: 1; Value2: 0.1W; SizeArea_mm2: 1.28; CompType: Resistor; AEC Qualified: Y; VDC_V: 75V; AEC Category: Q200; AEC Grade: 0
TP200 TP201 = 5000: Test Point, Miniature, Red, TH; Manufacturer: Keystone; CompType: Test Point Loop; ContactFinish: Silver; Green_Lifecycle: Active; Green_REACh: Passed
U200 U204 U208 = CMP-0040149-1: IC OPAMP VFB 45MHZ RRO SOT23-5; PartNumber: LMV116MF/NOPB; Manufacturer: Texas Instruments; BW @ Acl(MHz): 205; Io(Typ)(mA): 50; 3rd Harmonic(dBc): 105; Number of Channels: 1; Iib(Max)(nA): 1000; 2nd Harmonic(dBc): 85
U201 = TLV71333PQDBVRQ1: Capacitor-Free, 150-mA, Low-Dropout Regulator with Foldback Current Limit for Portable Devices, DBV0005A; Manufacturer: Texas Instruments; SymbolCreator: Altium; SizeArea_mm2: 8.12; SizeAreaWB_mm2: 14.82; SizeX_mm: 2.8; SizeY_mm: 2.9; SizeZ_mm: 1.45; CompType: IC; U/M: EA
U202 = CMP-0066190-1: Low-Drift, Low-Power, Dual-Output VREF and VREF/2 Voltage Reference, DDC0005A (SOT-23-T-5); Alternate PartNumber: REF2033AIDDCT; Alternate Manufacturer: Texas Instruments; SizeAreaWB_mm2: 14.82; U/M: EA; SizeZ_mm: 1.1; SizeX_mm: 2.8; SizeY_mm: 2.9; SizeArea_mm2: 8.12; CompType: IC
U203 U206 U207 = CMP-0040888-1: Precision, 20 MHz, 0.9 pA Ib, RRIO, CMOS Operational Amplifier, 1.8 to 5.5 V, -40 to 125 degC, 5-pin SOT23 (DBV5), Green (RoHS & no Sb/Br); Manufacturer: Texas Instruments; CMRR(Min)(dB): 100; Iq per channel(Max)(mA): 1.75; IIB(Max)(pA): 0.9; Total Supply Voltage(Min)(+5V is 5, +/-5V is 10): 1.8; Sub Family: High Output Current Amplifier (>=50mA), Low Input Bias Current Amp (<=10pA), Low Noise Amp (<=10nV/rtHz), Low Offset Voltage Amplifier (<=500uV), Low Supply Voltage Amplifier (<=2.7V), Precision Amplifier; Number of Channels: 2; Total Supply Voltage(Max)(+5V is 5, +/-5V is 10): 5.5; Offset Drift(Typ)(uV/C): 1.5; Vn at 1kHz(Typ)(nV/rtHz): 8.5; Slew Rate(Typ)(V/us): 10; Vio (25C)(Max)(mV): 0.15
U205 = CMP-0080587-1: Precision Reinforced Isolated Amplifier for Current Sensing, DWV0008A (SOIC-8); Alternate Manufacturer: Texas Instruments; SizeAreaWB_mm2: 105.975; SizeZ_mm: 2.8; SizeX_mm: 11.5; SizeY_mm: 5.85; SizeArea_mm2: 67.275; CompType: IC; AEC Qualified: Y; AEC Category: Q200
U209 = CMP-0078341-1: Precision, 2-V Input, Reinforced Isolated Amplifier, DWV0008A (SOIC-8); Alternate Manufacturer: Texas Instruments; SizeAreaWB_mm2: 105.975; SizeZ_mm: 2.8; SizeX_mm: 11.5; SizeY_mm: 5.85; SizeArea_mm2: 67.275; CompType: IC; AEC Qualified: N; AEC Category: Q200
